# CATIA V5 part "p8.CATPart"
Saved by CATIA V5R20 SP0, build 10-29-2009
Part number: p8
Publications: "Line.1", "Line.2", "Line.3", "Plane.1", "Plane.2"
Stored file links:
  D:\Dropbox\IAO_2011\MMS_GR2\IAO_2011_1439_jlicbarski\p8.CATPart
  D:\Dropbox\IAO_2011\MMS_GR2\IAO_2011_1439_jlicbarski\train.CATProduct

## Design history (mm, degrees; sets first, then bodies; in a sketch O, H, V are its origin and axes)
AxisSystem1: origin (0, 0, 0), X (1, 0, 0), Y (0, 1, 0), Z (0, 0, 1)
Set1
  Point1: linked copy from another document
  Point2: linked copy from another document
Body1 (main body)
  Line1: type PtPt, FirstPoint Point1, SecondPoint Point2
  Line2: type PtDir, RefPoint Point2, Direction edge [XY plane of AxisSystem1 | ZX plane of AxisSystem1], Start 0, End -15
  Line3: type PtDir, RefPoint Point1, Direction edge [XY plane of AxisSystem1 | ZX plane of AxisSystem1], Start 0, End -15
  Plane1: type Normal, Curve Line2
  Plane2: type Normal, Curve Line3, RefPoint Point1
